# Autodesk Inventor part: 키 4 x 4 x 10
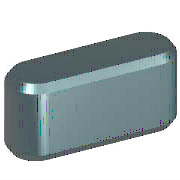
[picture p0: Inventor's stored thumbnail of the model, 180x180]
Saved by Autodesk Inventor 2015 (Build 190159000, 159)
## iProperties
IsCustomPart: 1
Created: 2012-02
Part Number: 키 4 x 4 x 10
Material: 강철, 연강
Description: 키 및 해당 키홈
Document SubType Name: Modeling
Standard: KS B 1311
Designer: test
Standards Organization: KS
Language: ko-KR
Size Designation: 4 x 4 x 10
Categories: <MemberInstance><Categories><Category DisplayName="샤프트 부품" InternalName="7f7aeb1f-a693-4053-b835-cee3144e0d98" Mnemonic="SHFT"><Category DisplayName="키" Interna
Density: 1 g/cm^3
Appearance: 노란색
Author: test
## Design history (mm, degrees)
workplane "Work Plane1"
workplane "Work Plane2"
sketch "스케치1"
  geometry: L1 (2, 2)-(8, 2); L2 (8, -2)-(2, -2); L3 (0, 9.4)-(0, -7.4) reference; L4 (-5, 0)-(30, 0) reference; L5 (10, 0)-(10, 7); A1 r 2 centre (2, 0) between (2, 2) and (2, -2); A2 r 2 centre (8, 0) between (8, -2) and (8, 2)
  constraints: 6 end point, 5 point on circle, 4 tangent, 3 point on line, 2 centre point, 1 horizontal, 1 parallel, 1 perpendicular
  dimensions: "d0" = 2 radius of A1 (= 0.5 x PB); "d13" = 2 radius of A2 (= 0.5 x PB); "d14" = 10 distance between parallel lines of L5 L3 (= NLG)
extrude "본체1" new body sketch "스케치1" taper "d3" = 0 deg; stored distance "d4" = 10
workplane "Work Plane3"
body "Solid1"
chamfer "모따기1" distance "d8" = 0.25 (= PHH); stored, may be unused: second distance "d9" = 0.25 (= PHH), angle "d15" = 45 deg
other parameters: "d1" = -2.5 (= -PNT), "d2" = 1.5 (= PH - PNT), "NLG" = 10 [user parameter; used in 3 equation terms], "PB" = 4 [user parameter; used in 2 equation terms], "PNT" = 2.5 [user parameter; used in 2 equation terms], "PH" = 4 [user parameter; used in 1 equation term], "PHH" = 0.25 [user parameter; used in 2 equation terms], "d10" = 0, "d16" = 0, "d17" = 0, "d18" = 0, "WDMAX" = 12 [user parameter], "RR" = 0.08 [user parameter], "PUEB" = 1.8 [user parameter]
